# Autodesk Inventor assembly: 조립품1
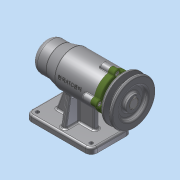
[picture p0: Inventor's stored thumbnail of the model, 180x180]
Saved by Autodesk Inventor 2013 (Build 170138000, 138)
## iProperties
Created: 2019-07
Part Number: 조립품1
Document SubType Name: Assembly
Designer: dgall
Author: dgall
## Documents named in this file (12)
- C:\Users\dgall\Desktop\490704v1040\조립품1.iam
- C:\Users\dgall\Desktop\490704v1040\1번 본체.ipt
- C:\Users\dgall\Desktop\490704v1040\V벨트풀리.ipt
- C:\Users\dgall\Desktop\490704v1040\멈춤나사 M3.ipt
- C:\Users\dgall\Desktop\490704v1040\베어링 6004.ipt
- C:\Users\dgall\Desktop\490704v1040\베어링 51202.ipt
- C:\Users\dgall\Desktop\490704v1040\볼트 M4.ipt
- C:\Users\dgall\Desktop\490704v1040\어댑터슬리브.ipt
- C:\Users\dgall\Desktop\490704v1040\오일 실.ipt
- C:\Users\dgall\Desktop\490704v1040\축.ipt
- C:\Users\dgall\Desktop\490704v1040\커버.ipt
- C:\Users\dgall\Desktop\490704v1040\키 5 x 5 x 16.ipt
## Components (2 placed, 2 different names)
1. 1번 본체:1
2. V벨트풀리:1
